// Mitsubishi GX Works2 project: FX3G_COM2_ADPRW 主站   PLC: FX3G

PROGRAM MAIN
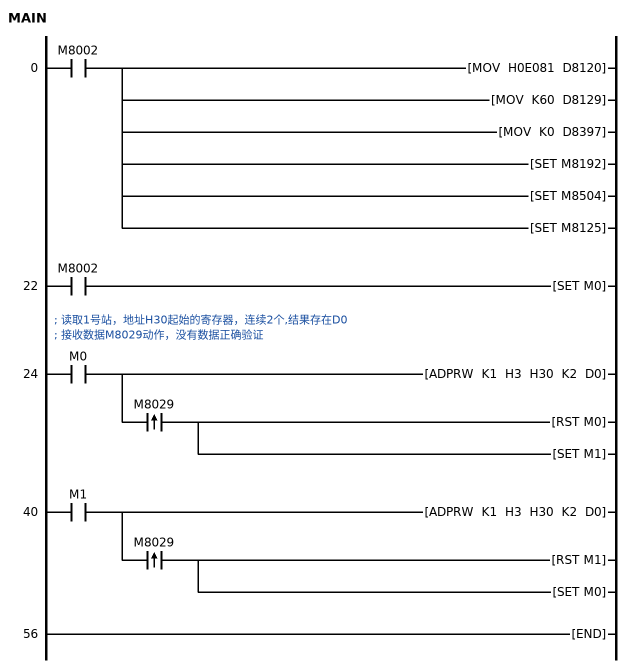
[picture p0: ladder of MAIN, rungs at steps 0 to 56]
0     LD      M8002
      MOV     H0E081 D8120
        [note] 通讯设定9600 8 N 1
      MOV     K60 D8129
        [note] RD3A通讯超时设定
      MOV     K0 D8397
        [note] ADPRW串口2切换
      SET     M8192
        [note] 485模式
      SET     M8504
        [note] RD3A开启
      SET     M8125
        [note] 启用modbus功能
22    LD      M8002
      SET     M0
; 读取1号站，地址H30起始的寄存器，连续2个,结果存在D0
; 接收数据M8029动作，没有数据正确验证
24    LD      M0
      ADPRW   K1 H3 H30 K2 D0
      ANDP    M8029
      RST     M0
      SET     M1
40    LD      M1
      ADPRW   K1 H3 H30 K2 D0
      ANDP    M8029
      RST     M1
      SET     M0
56    END
END_PROGRAM

// device comments not shown above
D200  ; 写入数量，1个
D211  ; 转速
M2  ; 反转
M3  ; 停止
